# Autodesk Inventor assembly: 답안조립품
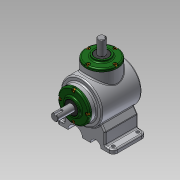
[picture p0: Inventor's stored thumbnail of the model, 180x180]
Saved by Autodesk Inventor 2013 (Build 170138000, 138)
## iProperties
Created: 2018-08
Part Number: 답안조립품
Document SubType Name: Assembly
Designer: hana-cad38
Author: hana-cad38
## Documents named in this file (14)
- C:\Documents and Settings\hana-cad38\바탕 화면\480808V1005\답안조립품.iam
- C:\Documents and Settings\hana-cad38\바탕 화면\480808V1005\본체.ipt
- C:\Documents and Settings\hana-cad38\바탕 화면\480808V1005\커버.ipt
- C:\Documents and Settings\hana-cad38\바탕 화면\480808V1005\베어링 6203.ipt
- C:\Documents and Settings\hana-cad38\바탕 화면\480808V1005\오일실 17 32 8.ipt
- C:\Documents and Settings\hana-cad38\바탕 화면\480808V1005\메인 축.ipt
- 메인 축.ipt
- C:\Documents and Settings\hana-cad38\바탕 화면\480808V1005\서브 축.ipt
- 서브 축.ipt
- C:\Documents and Settings\hana-cad38\바탕 화면\480808V1005\키 5x5.ipt
- C:\Documents and Settings\hana-cad38\바탕 화면\480808V1005\키 4x4.ipt
- C:\Documents and Settings\hana-cad38\바탕 화면\480808V1005\메인 베벨기어.ipt
- C:\Documents and Settings\hana-cad38\바탕 화면\480808V1005\서브 베벨기어.ipt
- C:\Documents and Settings\hana-cad38\바탕 화면\480808V1005\볼트 M4.ipt
